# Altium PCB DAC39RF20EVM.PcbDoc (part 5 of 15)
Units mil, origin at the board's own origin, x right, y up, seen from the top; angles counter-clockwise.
Board outline 6200 x 2716.54 mil, 16 copper layers (Top Layer, L2 GND, L3 PWR, L4 GND, L5 PWR, L6 GND, L7 SIG, L8 GND, L9 GND, L10 SIG, L11 GND, L12 PWR, L13 GND, L14 PWR, L15 GND, Bottom Layer), stack 76.97 mil thick; 766 components, 495 nets, 3414 pads, 2373 vias.
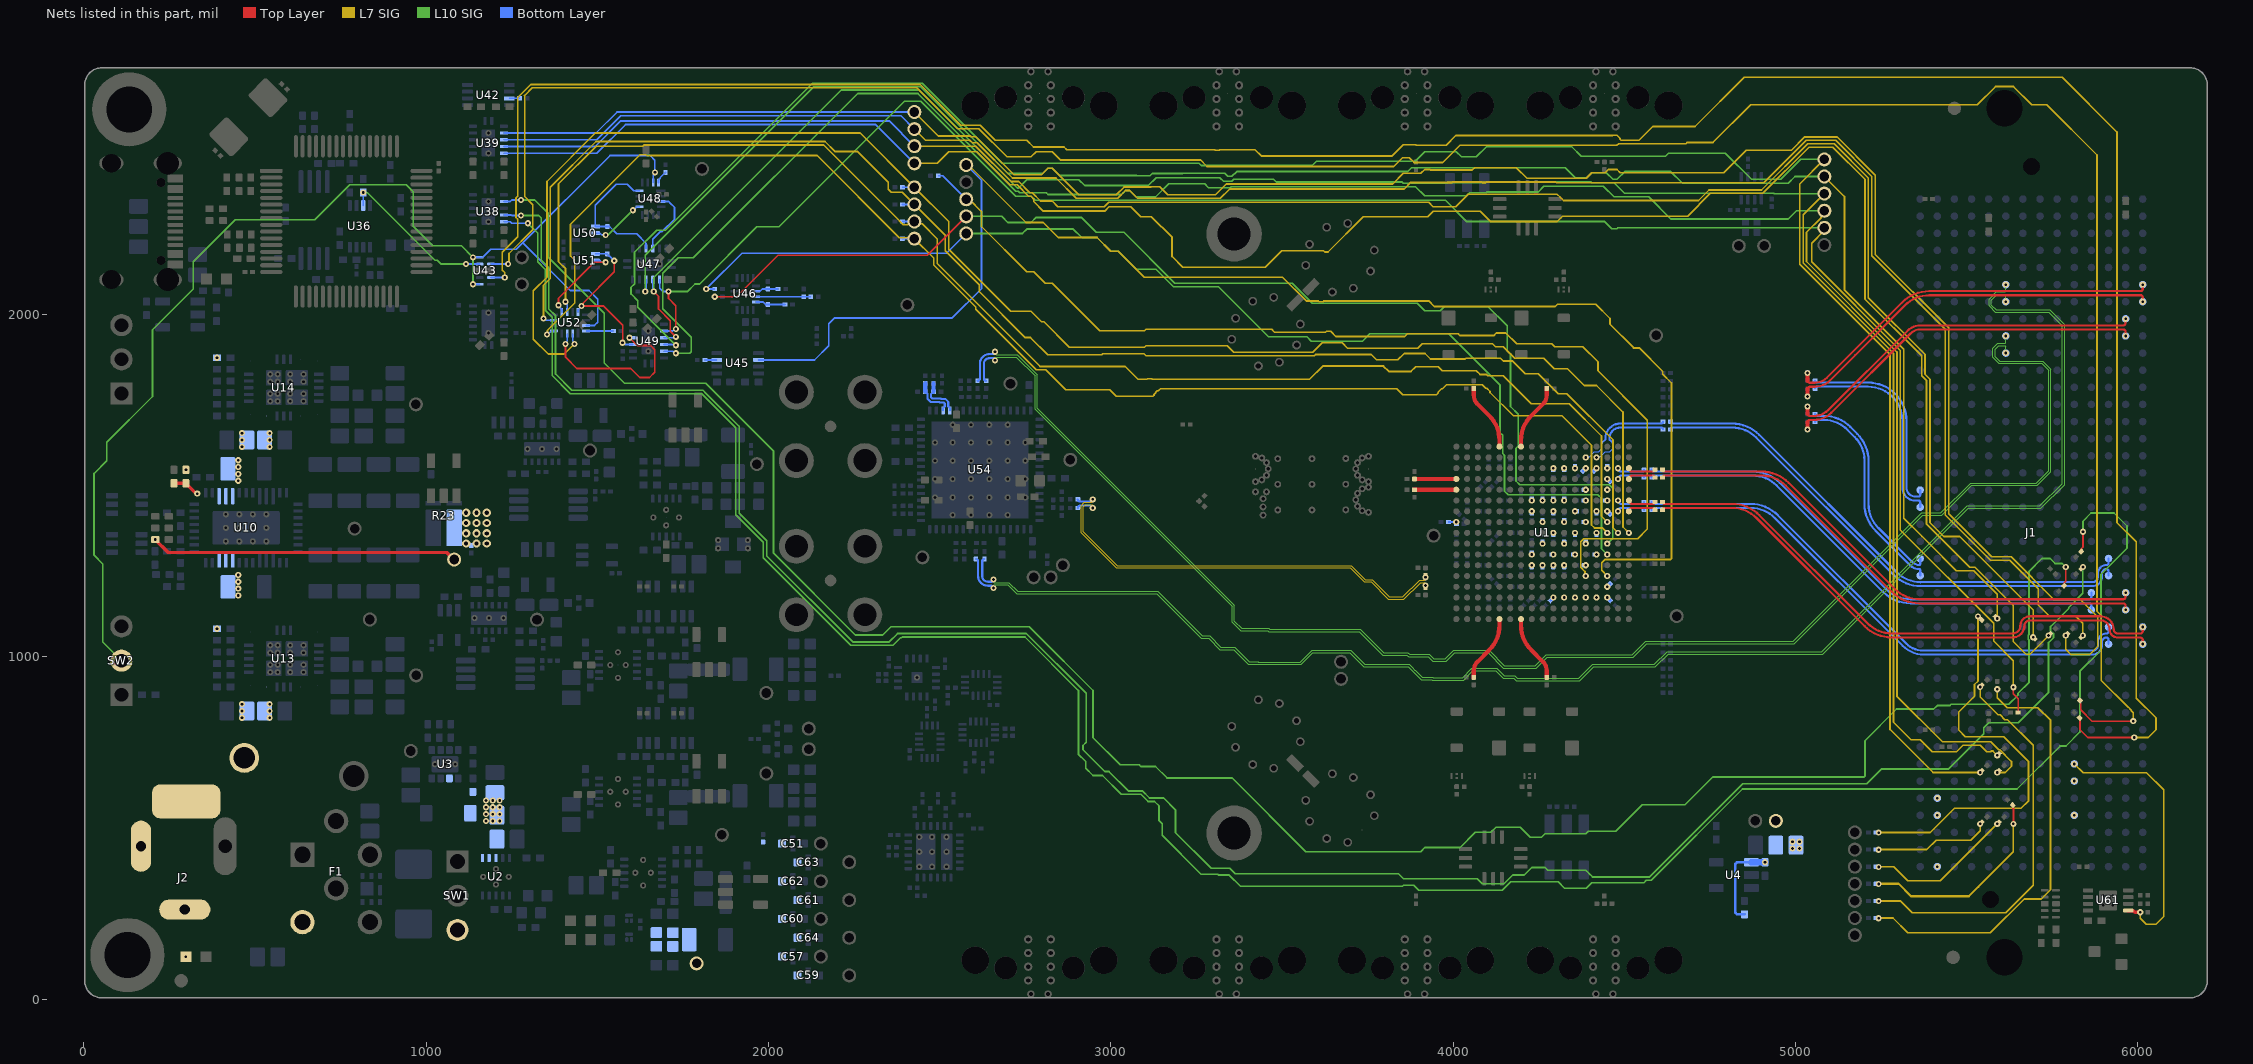
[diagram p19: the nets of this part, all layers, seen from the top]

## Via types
v1: diameter 18, hole 8, Top Layer to Bottom Layer, tented both sides, 2344 vias
v2: diameter 24, hole 12, Top Layer to Bottom Layer, tented both sides, 19 vias
v3: diameter 18, hole 8, Top Layer to Bottom Layer, tented bottom, 9 vias
v4: diameter 20, hole 10, Top Layer to Bottom Layer, tented both sides, 1 vias

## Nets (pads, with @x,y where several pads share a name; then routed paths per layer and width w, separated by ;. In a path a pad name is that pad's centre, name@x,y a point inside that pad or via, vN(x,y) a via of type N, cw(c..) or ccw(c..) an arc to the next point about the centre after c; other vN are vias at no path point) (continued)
11SRX_DUT_n: C208.1 U1.T4 | length 269.4
  Bottom Layer w3.4: 4448.05,1598.19 4456.65,1598.19 4465.77,1607.3 4465.77,1624.99
  Bottom Layer w3.5: v1(4418.48,1582.44) 4420.44,1584.41 4429.66,1584.41 4443.45,1598.19 4448.05,1598.19
  Bottom Layer w5.6: 4456.86,1633.65 4465.77,1624.99 4465.82,1624.93
  Bottom Layer w6.3: 4456.26,1634.24 4456.26,1637.85 cw(c4487.95,1637.85) 4487.95,1669.54 4607.36,1669.54 cw(c4607.36,1663.94) C208.1@4612.96,1663.94
11SRX_DUT_p: C207.1 U1.T5 | length 288.3
  Bottom Layer w3.4: 4416.56,1598.19 4425.16,1598.19 4434.27,1607.3 4434.27,1624.99
  Bottom Layer w3.5: v1(4386.98,1582.44) 4388.95,1584.41 4398.17,1584.41 4411.95,1598.19 4416.55,1598.19
  Bottom Layer w5.6: 4434.32,1624.93 4443.87,1633.73
  Bottom Layer w6.3: 4444.46,1634.33 4444.46,1637.85 cw(c4487.95,1637.85) 4487.95,1681.34 4607.36,1681.34 ccw(c4607.36,1686.94) C207.1@4612.96,1686.94
11SRX_n: C208.2 J1.A23 | length 1513.7
  Bottom Layer w6.3: C208.2@4635.01,1663.94 cw(c4640.61,1663.94) 4640.61,1669.54 4814.42,1669.54 cw(c4814.42,1569.54) 4885.13,1640.25 5286.25,1239.13 ccw(c5365.31,1318.18) 5365.31,1206.38 5867.19,1206.38 ccw(c5867.18,1234.25) 5895.03,1234.25 5895.03,1243.49 cw(c5907.71,1243.49) 5907.71,1256.17 cw(c5907.71,1249.86) 5914.01,1249.86 J1.A23@5914.01,1237.07
11SRX_p: C207.2 J1.A22 | length 1513.8
  Bottom Layer w6.3: C207.2@4635.01,1686.94 ccw(c4640.61,1686.94) 4640.61,1681.34 4814.42,1681.34 cw(c4814.42,1569.54) 4893.48,1648.59 5294.6,1247.47 ccw(c5365.31,1318.18) 5355.48,1218.67 5362.13,1218.01 ccw(c5364.01,1237.07) 5366.78,1218.12 cw(c5367.68,1211.88) 5367.68,1218.18 5867.19,1218.18 ccw(c5864.01,1237.07) 5867.31,1218.2 ccw(c5867.31,1234.12) 5883.23,1234.12 5883.23,1243.49 cw(c5907.71,1243.49) 5907.71,1267.97 ccw(c5907.71,1274.27) 5914.01,1274.27 J1.A22@5914.01,1287.07
12SRX_DUT_n: C210.1 U1.P1 | length 85
  Top Layer w6.3: U1.P1@4512.96,1519.45 cw(c4522.81,1519.45) 4522.81,1529.3 4583.51,1529.3 cw(c4583.51,1523.65) C210.1@4589.16,1523.65
12SRX_DUT_p: C209.1 U1.R1 | length 85
  Top Layer w6.3: U1.R1@4512.96,1550.94 ccw(c4522.81,1550.94) 4522.81,1541.1 4583.61,1541.1 ccw(c4583.61,1546.65) C209.1@4589.16,1546.65
12SRX_n: C210.2 J1.Z25 | length 1517.4
  Top Layer w6.3: C210.2@4611.21,1523.65 cw(c4616.81,1523.65) 4616.81,1529.25 4900.54,1529.25 cw(c4900.54,1429.25) 4971.25,1499.96 5282.29,1188.91 ccw(c5361.35,1267.97) 5361.35,1156.17 5956.65,1156.17 cw(c5956.65,1148.8) 5964.01,1148.8 v1(5964.01,1137.07)
12SRX_p: C209.2 J1.Z24 | length 1517.4
  Top Layer w6.3: C209.2@4611.21,1546.65 ccw(c4616.81,1546.65) 4616.81,1541.05 4900.54,1541.05 cw(c4900.54,1429.25) 4979.59,1508.3 5290.64,1197.26 ccw(c5361.35,1267.97) 5361.35,1167.97 5956.65,1167.97 ccw(c5956.65,1175.33) 5964.01,1175.33 v1(5964.01,1187.07)
12V: C2.2 C3.2 C6.2 C7.2 C20.2 C21.2 C32.2 C33.2 C40.2 C41.2 D1.1 D3.1 pad.1@2940.17,477.52 R7.1 R8.2 R9.2 R21.2 R34.2 R39.2 U2.6 U2.7 U2.8 U3.2 U4.1 U10.4 U10.5 U10.6 U10.33 U10.34 U10.35 U13.18 U14.18 | length 259.4
  Bottom Layer w8: R9.2@4850.49,247.76 4829.33,247.76 4824.08,253.02 4824.08,395.2 4828.76,399.89 U4.1@4870.77,399.89
  Bottom Layer w20: U4.1@4870.77,399.89 v1(4910.77,399.89)
  other v1: 297.92,123.65 4991.22,439.74 5011.22,439.74 4991.22,459.74 5011.22,459.74 1174.67,520.44 1194.67,520.44 1214.67,520.44 1174.67,540.44 1194.67,540.44 1214.67,540.44 1174.67,560.44 1194.67,560.44 1214.67,560.44 1174.67,580.44 1194.67,580.44 1214.67,580.44 461.82,821.74 542.82,821.74 461.82,841.74 542.82,841.74 461.82,861.74 542.82,861.74 389.38,1082.11 450.94,1179.07 450.94,1199.07 450.94,1219.07 450.94,1239.07 450.94,1514.11 450.94,1534.11 298.22,1546.25 450.94,1554.11 450.94,1574.11 461.82,1613.27 542.82,1613.27 461.82,1633.27 542.82,1633.27 461.82,1653.27 542.82,1653.27 389.38,1873.64
12V_FMC: J1.C35 J1.C37 J1.L36 J1.L37 J1.L40 pad.1@3598.23,258.31 SW1.3
  other v1: 5414.01,387.07 5414.01,537.07 5814.01,537.07 5414.01,587.07 5814.01,637.07
13SRX_DUT_n: C212.1 U1.P2 | length 85
  Bottom Layer w6.3: v1(4481.47,1519.45) cw(c4491.32,1519.45) 4491.32,1529.3 4552.07,1529.3 cw(c4552.07,1523.7) C212.1@4557.67,1523.7
13SRX_DUT_p: C211.1 U1.R2 | length 85
  Bottom Layer w6.3: v1(4481.47,1550.94) ccw(c4491.32,1550.94) 4491.32,1541.1 4552.07,1541.1 ccw(c4552.07,1546.7) C211.1@4557.67,1546.7
13SRX_n: C212.2 J1.B25 | length 1449.6
  Bottom Layer w6.3: C212.2@4579.48,1523.7 cw(c4585.08,1523.7) 4585.08,1529.3 4874.43,1529.3 cw(c4874.43,1429.3) 4945.14,1500.01 5256.23,1188.91 ccw(c5335.29,1267.97) 5335.29,1156.17 5857.71,1156.17 cw(c5857.71,1149.86) 5864.01,1149.86 J1.B25@5864.01,1137.07
13SRX_p: C211.2 J1.B24 | length 1449.6
  Bottom Layer w6.3: C211.2@4579.48,1546.7 ccw(c4585.08,1546.7) 4585.08,1541.1 4874.43,1541.1 cw(c4874.43,1429.3) 4953.48,1508.35 5264.58,1197.26 ccw(c5335.29,1267.97) 5335.29,1167.97 5857.71,1167.97 ccw(c5857.71,1174.27) 5864.01,1174.27 J1.B24@5864.01,1187.07
14SRX_DUT_n: C214.1 U1.L1 | length 85
  Top Layer w6.3: U1.L1@4512.96,1424.96 cw(c4522.81,1424.96) 4522.81,1434.81 4583.51,1434.81 cw(c4583.51,1429.16) C214.1@4589.16,1429.16
14SRX_DUT_p: C213.1 U1.M1 | length 85
  Top Layer w6.3: U1.M1@4512.96,1456.46 ccw(c4522.81,1456.46) 4522.81,1446.61 4583.61,1446.61 ccw(c4583.61,1452.16) C213.1@4589.16,1452.16
14SRX_n: C214.2 J1.Y27 | length 1626.6
  Top Layer w6.3: C214.2@4611.21,1429.16 cw(c4616.81,1429.16) 4616.81,1434.76 4815.01,1434.76 cw(c4815.01,1334.76) 4885.72,1405.47 5201.81,1089.39 ccw(c5280.86,1168.44) 5280.86,1056.64 5634.52,1056.64 ccw(c5634.52,1090.22) 5668.1,1090.22 cw(c5684.31,1090.22) 5684.31,1106.43 5890.92,1106.43 cw(c5890.92,1080.06) 5917.28,1080.06 ccw(c5941.18,1080.06) 5941.18,1056.17 6006.65,1056.17 cw(c6006.65,1048.8) 6014.01,1048.8 v1(6014.01,1037.07)
14SRX_p: C213.2 J1.Y26 | length 1626.6
  Top Layer w6.3: C213.2@4611.21,1452.16 ccw(c4616.81,1452.16) 4616.81,1446.56 4815.01,1446.56 cw(c4815.01,1334.76) 4894.07,1413.81 5210.15,1097.73 ccw(c5280.86,1168.44) 5280.86,1068.44 5634.52,1068.44 ccw(c5634.52,1090.22) 5656.3,1090.22 cw(c5684.31,1090.22) 5684.31,1118.23 5890.92,1118.23 cw(c5890.92,1080.06) 5929.08,1080.06 ccw(c5941.18,1080.06) 5941.18,1067.97 6006.65,1067.97 ccw(c6006.65,1075.33) 6014.01,1075.33 v1(6014.01,1087.07)
15SRX_DUT_n: C216.1 U1.L2 | length 85
  Bottom Layer w6.3: v1(4481.47,1424.96) cw(c4491.32,1424.96) 4491.32,1434.81 4552.07,1434.81 cw(c4552.07,1429.21) C216.1@4557.67,1429.21
15SRX_DUT_p: C215.1 U1.M2 | length 85
  Bottom Layer w6.3: v1(4481.47,1456.46) ccw(c4491.32,1456.46) 4491.32,1446.61 4552.07,1446.61 ccw(c4552.07,1452.21) C215.1@4557.67,1452.21
15SRX_n: C216.2 J1.A27 | length 1555.8
  Bottom Layer w6.3: C216.2@4579.72,1429.21 cw(c4585.31,1429.21) 4585.31,1434.81 4868.79,1434.81 cw(c4868.79,1334.81) 4939.5,1405.52 5313.14,1031.88 ccw(c5374.65,1093.4) 5374.65,1006.4 5867.18,1006.4 ; J1.A27@5914.01,1037.07 5914.01,1049.86 ccw(c5907.71,1049.86) 5907.71,1056.17 ccw(c5907.71,1043.49) 5895.03,1043.49 5895.03,1034.25 cw(c5867.18,1034.25) 5867.31,1006.4 ; 5867.18,1006.4 ccw(c5867.18,1034.25) 5867.31,1006.4 ; 5867.18,1006.4 5867.31,1006.4
15SRX_p: C215.2 J1.A26 | length 1555.9
  Bottom Layer w6.3: C215.2@4579.72,1452.21 ccw(c4585.31,1452.21) 4585.31,1446.61 4868.79,1446.61 cw(c4868.79,1334.81) 4947.85,1413.86 5322.93,1038.78 ccw(c5372.6,1088.46) 5372.6,1018.2 5867.31,1018.2 ccw(c5867.31,1034.12) 5883.23,1034.12 5883.23,1043.49 cw(c5907.71,1043.49) 5907.71,1067.97 ccw(c5907.71,1074.27) 5914.01,1074.27 J1.A26@5914.01,1087.07
+1p8V: C51.1 C53.2 C54.2 C55.2 C56.2 C57.1 C59.1 C60.1 C61.1 C62.1 C63.1 C64.1 FB3.2 PP14.1 R43.1
C8_N: C171.2 R167.2 U54.52 | length 127.2
  Bottom Layer w6.3: R167.2@2481.85,1774.06 2481.06,1774.06 2474.91,1767.9 2474.91,1758.31 2478.6,1754.62 2502.76,1754.62 2503.9,1753.48 2516.01,1753.48 2524.91,1744.59 2524.91,1730.64 2529.6,1725.95 U54.52@2529.6,1719.06
  Bottom Layer w12.1: R167.2@2481.85,1774.06 C171.2@2481.85,1799.06
C8_P: C170.2 R166.2 U54.51 | length 127.2
  Bottom Layer w6.3: R166.2@2457.67,1774.06 2458.45,1774.06 2464.61,1767.9 2464.61,1754.04 2474.33,1744.32 2498.5,1744.32 2499.63,1743.18 2511.74,1743.18 2514.61,1740.32 2514.61,1730.64 2509.92,1725.95 U54.51@2509.92,1719.06
  Bottom Layer w12.1: R166.2@2457.67,1774.06 C170.2@2457.67,1799.06
CCLK_SHIFT: R199.1 U38.14 | length 7112
  Top Layer w5: R199.1@5834.82,1313.25 R199.1@5834.31,1307.36 5834.86,1307.92 5834.86,1316.31 5839.32,1320.76 v3(5839.32,1365.17)
  L10 SIG w5: v1(1297.12,2266.32) 1325.64,2237.8 1325.64,2154.13 1348.36,2131.42 1348.36,2011.71 1368.04,1992.03 1368.04,1821.72 1421.02,1768.73 1804.5,1768.73 1904.37,1668.86 1904.37,1414.88 1984.81,1334.45 1984.81,1289.12 2240.49,1033.44 2363.77,1033.44 2385.55,1055.23 2387.51,1055.23 2390.28,1057.99 2748.98,1057.99 2905.22,901.76 2905.22,715.62 2926.52,694.32 2926.52,674.67 2947.83,653.37 2975.52,653.37 3030.61,598.28 3087.87,598.28 3108.66,577.49 3127.51,577.49 3140.85,564.15 3140.85,521.17 3149.97,512.05 3149.97,478.41 3263.16,365.22 3312.26,365.22 3315.08,362.4 3346.1,362.4 3378.76,329.74 3851.4,329.74 3854.72,333.05 3884.16,333.05 3899.32,317.89 4143.1,317.89 4168.11,342.9 4306.47,342.9 4325.02,324.35 4388.63,324.35 4404.48,340.21 4557.15,340.21 4564.03,347.09 4578.17,347.09 4844.79,613.71 5646.83,613.71 5772.57,739.45 5789.73,739.45 5830.51,780.23 5830.51,958.21 5891.94,1019.64 5891.94,1240.6 5968.05,1316.71 5968.05,1382.18 5930.22,1420.01 5863.05,1420.01 5839.32,1396.28 v3(5839.32,1365.17)
  Bottom Layer w5: U38.14@1227.12,2270.82 1245.54,2270.82 1250.04,2266.32 v1(1297.12,2266.32)
COMM_MUX_CTRL: SW2.1 U43.1 U43.5 U48.15 U52.15 | length 3594.9
  L10 SIG w5: SW2.1@110.07,988.8 55.54,1043.33 55.54,1270.86 30.09,1296.31 30.09,1535.41 67.3,1572.61 67.3,1626.74 200.74,1760.19 200.74,1955.14 319.86,2074.26 319.86,2154.03 442.44,2276.61 674.3,2276.61 776.63,2378.94 809.46,2378.94 942.2,2378.94 962.59,2358.54 962.59,2257.4 1019.77,2200.22 1103.12,2200.22 v1(1136.57,2166.77) v1(1136.57,2088.03)
  Bottom Layer w5: v1(1136.57,2088.03) U43.1@1156.57,2088.03 ; v1(1136.57,2166.77) U43.5@1156.57,2166.77 1164.93,2166.77 1188.43,2190.27 1263.35,2190.27 1282,2208.91 ; U52.15@1467.36,1967.47 1491.42,1967.47 1501.4,1977.45 1501.4,2043.9 1475.54,2069.75 1421.16,2069.75 1287.67,2203.24 1282,2208.91 ; U48.15@1663.11,2384.99 1663.11,2406.48 1668.11,2411.48 v1(1668.11,2414.99) 1668.11,2450.49 1653.89,2464.71 1649.75,2464.71 1649.2,2464.16 1537.24,2464.16 1282,2208.91
DAC_ALARM: PP56.1 U1.E3 U45.6 | length 4267.9
  L7 SIG w5: PP56.1@2577.51,2436.45 2584,2436.45 2752.11,2268.34 2802.58,2268.34 2846.31,2224.6 2959.58,2224.6 2999.22,2184.97 3021.62,2184.97 3097.57,2109.03 3501.49,2109.03 3571.03,2039.49 3605.64,2039.49 3607.89,2037.24 3619.9,2037.24 3622.15,2039.49 3928.53,2039.49 3944.93,2023.09 4298,2023.09 4304.68,2029.77 4416.5,2029.77 4458.03,1988.24 4458.03,1970.98 4526.8,1902.21 4543.26,1902.21 4612.03,1833.44 4612.03,1825.28 4637.61,1799.71 4637.61,1287.41 4634.68,1284.48 4443.63,1284.48 4433.47,1274.31 4433.47,1252.48 v1(4449.97,1235.98)
  Bottom Layer w5: U45.6@1971.03,1867.08 2134.21,1867.08 2175.99,1908.85 2175.99,1972.47 2193.33,1989.82 2534.02,1989.82 2535.13,1988.71 2621.96,2075.54 2621.96,2392 PP56.1@2577.51,2436.45
DAC_ALARM_FMC: R210.1 U45.3 | length 35
  Bottom Layer w5: R210.1@1813.98,1867.08 U45.3@1848.98,1867.08
DAC_C\S\: PP45.1 R151.2 U1.K3 U52.10 | length 4219.5
  L7 SIG w5: v1(1407.24,2036.84) 1407.24,2133.05 1386.49,2153.8 1386.49,2381.45 1496.43,2491.38 1632.57,2491.38 1636.36,2495.16 2160.72,2495.16 2370,2285.88 2370.08,2285.88 2393.83,2262.14 2407.14,2262.14 2416.38,2271.38 PP45.1@2426.12,2271.38 2433.01,2264.49 2448.58,2264.49 2492.73,2220.34 2492.73,2148.61 2793.22,1848.12 3041.68,1848.12 3079.31,1810.49 3105,1810.49 3107.04,1812.53 3119.05,1812.53 3121.09,1810.49 3580.16,1810.49 3618.78,1849.11 3796.01,1849.11 3811.53,1833.59 3876.8,1833.59 3890.67,1847.46 3955.94,1847.46 3967.64,1835.76 4067.17,1835.76 4078.09,1824.84 4096.13,1824.84 4100.37,1820.59 4145.7,1820.59 4227.43,1738.86 4339.17,1738.86 4432.98,1645.06 4432.98,1410.46 v1(4449.97,1393.46)
  Bottom Layer w5: v1(1407.24,2036.84) 1407.24,2033.33 1412.24,2028.33 U52.10@1412.24,2006.84 ; R151.2@2391.12,2271.38 PP45.1@2426.12,2271.38
DAC_R\E\S\E\T\: PP61.1 R135.2 U1.E5 | length 3060.8
  L7 SIG w5: PP61.1@2577.51,2336.45 2585.94,2336.45 2621.96,2300.42 2621.96,2256.86 2754.48,2124.34 2774.99,2124.34 2807.93,2091.4 2828.53,2091.4 2967.71,1952.22 3098.42,1952.22 3102.52,1956.32 3469.83,1956.32 3477.95,1948.2 3627.03,1948.2 3629.77,1950.94 3641.78,1950.94 3657.3,1935.42 3858.03,1935.42 3866.11,1943.49 4014.43,1943.49 4019.75,1938.16 4117.85,1938.16 4125.65,1945.96 4153.35,1945.96 4185.25,1914.07 4287.71,1914.07 4296.18,1905.6 4378.67,1905.6 4422.9,1861.37 4422.9,1835.25 4566.92,1691.23 4566.92,1373.11 4538.78,1344.97 4380.97,1344.97 4372.48,1336.48 4372.48,1261.47 4384.61,1249.34 4384.61,1238.35 v1(4386.98,1235.98)
  Bottom Layer w5: R135.2@2495.58,2404.99 2508.97,2404.99 PP61.1@2577.51,2336.45
DAC_R\E\S\E\T\_FMC: R134.2 R214.1 U46.12 | length 87.8
  Bottom Layer w5: U46.12@1963.15,2036.08 1984.22,2036.08 1991.07,2029.23 R134.2@1998.15,2029.23 R214.1@2048.15,2029.23
DAC_SCLK: PP42.1 R154.1 U1.J1 U52.2 | length 4678.2
  L7 SIG w5: v1(1432.99,1913.85) 1403.48,1884.34 1356.25,1884.34 1312.73,1927.87 1312.73,2068.77 1352.87,2108.92 1352.87,2388.46 1494.29,2529.88 2267.63,2529.88 PP42.1@2426.12,2371.38 2526.19,2271.32 2526.19,2190.3 2707.15,2009.34 2766.5,2009.34 2797.54,1978.29 2804.63,1978.29 2878.7,1904.22 3098.42,1904.22 3102.52,1908.32 3339.78,1908.32 3358.78,1889.32 3589.95,1889.32 3617.63,1916.99 3675.72,1916.99 3691.24,1901.47 3896.73,1901.47 3909.32,1914.07 4114.81,1914.07 4123.27,1905.6 4145.79,1905.6 4179.21,1872.19 4264.26,1872.19 4294.69,1841.76 4333.62,1841.76 4382.91,1792.46 4418.31,1792.46 4495.97,1714.81 4495.97,1378.96 v1(4512.96,1361.97)
  Bottom Layer w5: U52.2@1427.99,1943.85 1427.99,1922.37 1432.99,1917.37 v1(1432.99,1913.85) ; R154.1@2391.12,2371.38 PP42.1@2426.12,2371.38
DAC_SDI: PP43.1 R155.1 U1.J3 U52.5 | length 4186.7
  L7 SIG w5: v1(1352.87,1941.73) 1354.3,1943.15 1354.3,1953.64 1433.88,2033.22 1433.88,2158.58 1421.52,2170.94 1421.52,2262.95 1624.74,2466.16 1642.24,2466.16 1643.95,2464.45 2141.51,2464.45 2381.78,2224.19 2423.32,2224.19 PP43.1@2426.12,2221.38 2482.73,2164.77 2482.73,2144.47 2605.68,2021.53 2605.68,2014.95 2782.5,1838.12 2809.88,1838.12 2867.76,1780.24 2996.51,1780.24 3015.61,1761.13 3123.06,1761.13 3126.27,1764.35 3126.27,1767.18 3135.94,1776.84 3138.76,1776.84 3145.15,1783.23 3835.21,1783.23 3852.73,1765.71 3951.14,1765.71 3956.17,1770.74 3956.17,1773.57 3965.84,1783.23 3968.66,1783.23 3980.28,1794.85 4084.83,1794.85 4095.03,1784.65 4097.85,1784.65 4107.52,1774.99 4107.52,1772.16 4175.86,1703.81 4248.28,1703.81 4248.94,1704.47 4262.61,1704.47 4263.26,1703.81 4317.61,1703.81 4403.98,1617.45 4403.98,1385.08 4412.59,1376.47 4435.47,1376.47 v1(4449.97,1361.97)
  Bottom Layer w5: v1@1355,1941.73 1365,1951.73 U52.5@1372.87,1951.73 ; R155.1@2391.12,2221.38 PP43.1@2426.12,2221.38
DAC_SDO: PP44.1 R156.1 U1.J2 U52.7 | length 4329.8
  L7 SIG w5: v1(1342.87,1988.22) 1342.87,2084.78 1362.87,2104.78 1362.87,2371.97 1496.07,2505.16 2164.86,2505.16 2193.9,2476.13 2259.33,2476.13 2349.58,2385.88 2349.58,2365.38 2358.07,2356.88 2390.62,2356.88 PP44.1@2426.12,2321.38 2516.19,2231.32 2516.19,2186.16 2615.74,2086.61 2615.74,2066.83 2750.22,1932.36 2765.14,1932.36 2815.43,1882.07 2973.57,1882.07 2976.72,1885.22 3096.63,1885.22 3102.52,1879.32 3594.1,1879.32 3597.83,1883.05 3760.22,1883.05 3775.74,1867.53 3838.3,1867.53 3856.79,1886.02 3917.5,1886.02 3933.76,1869.76 4034.77,1869.76 4037.19,1872.19 4138.2,1872.19 4146.68,1863.7 4173.55,1863.7 4210.23,1827.02 4248,1827.02 4306.48,1768.54 4331.51,1768.54 4466.47,1633.58 4466.47,1376.96 v1(4481.47,1361.97)
  Bottom Layer w5: v1(1342.87,1988.22) 1346.39,1988.22 1351.39,1983.22 U52.7@1372.87,1983.22 ; R156.1@2391.12,2321.38 PP44.1@2426.12,2321.38
DAC_SYSREF_LMK_N: C163.1 R173.2 | length 1271.8
  Top Layer w8: v1(3919.03,1232.33) R173.2@3919.03,1237.33
  L7 SIG w3: v1(2946.87,1434.88) 2946.87,1442.15 2945.11,1443.9 2925.16,1443.9 2919.89,1438.64 2919.89,1365.56 3018.88,1266.58 3701.76,1266.58 3742.77,1225.57 3763.11,1225.57 3813.47,1175.22 3852.97,1175.22 3901.49,1223.74 3917.27,1223.74 3919.03,1225.49 v1(3919.03,1232.33)
  Bottom Layer w6.3: C163.1@2903.46,1434.88 cw(c2910.08,1434.88) 2910.08,1441.5 2940.24,1441.51 cw(c2940.24,1434.88) v1(2946.87,1434.88)
DAC_SYSREF_LMK_P: C162.1 R171.2 | length 1295
  Top Layer w8: R171.2@3919.03,1203.14 v1(3919.03,1208.14)
  L7 SIG w3: v1(2946.87,1459.93) 2946.87,1452.66 2945.11,1450.9 2922.26,1450.9 2912.89,1441.54 2912.89,1362.66 3015.98,1259.58 3698.86,1259.58 3739.87,1218.57 3760.21,1218.57 3810.57,1168.22 3855.87,1168.22 3904.39,1216.74 3917.27,1216.74 3919.03,1214.98 v1(3919.03,1208.14)
  Bottom Layer w6.3: C162.1@2903.46,1459.93 ccw(c2910.08,1459.93) 2910.08,1453.3 2940.24,1453.3 ccw(c2940.24,1459.93) v1(2946.87,1459.93)
DAC_TXEN0: PP63.1 R137.2 U1.G3 | length 3400.2
  L10 SIG w5: PP63.1@2577.51,2236.45 2741.6,2236.45 2754.48,2249.34 2890.08,2249.34 2914.82,2224.6 2959.58,2224.6 2999.22,2184.97 3021.62,2184.97 3074.7,2131.9 3131.84,2131.9 3182.9,2080.84 3314.44,2080.84 3460.28,1934.99 3572.68,1934.99 3585.74,1921.94 3735.11,1921.94 3756.67,1943.49 3987.34,1943.49 4136.38,1794.45 4136.38,1655.09 4144.36,1647.11 4144.36,1593.6 4149.51,1588.45 4149.51,1484.44 4160.5,1473.45 4421.99,1473.45 4432.98,1462.46 4432.98,1315.97 v1(4449.97,1298.98)
  Bottom Layer w5: v1(1818.11,2074.43) v1@1818.9,2074.43 ; R137.2@1843.11,2074.43 v1@1818.9,2074.43 ; PP63.1@2577.51,2236.45 2519.86,2178.8 1922.49,2178.8 1822.7,2079.01 1822.7,2078.22 v1@1818.9,2074.43
DAC_TXEN0_FMC: R132.2 R212.1 U46.10 | length 67.8
  Bottom Layer w5: U46.10@1963.15,2067.58 1974.96,2067.58 1981.81,2074.43 R132.2@1998.15,2074.43 R212.1@2028.15,2074.43
DAC_TXEN1: PP64.1 R136.2 U1.H3 | length 3495.8
  Top Layer w5: v1(1843.11,2051.83) 1906.44,2051.83 2027.51,2172.9 2463.96,2172.9 PP64.1@2577.51,2286.45
  L10 SIG w5: PP64.1@2577.51,2286.45 2680.85,2286.45 2698.96,2268.34 2766.5,2268.34 2781.55,2283.4 2913.75,2283.4 2957.41,2239.74 3038.14,2239.74 3187.05,2090.84 3529.89,2090.84 3588.42,2032.3 3894.71,2032.3 3916.52,2010.49 3962.12,2010.49 3974.03,2022.4 4101.44,2022.4 4129.4,1994.43 4130.05,1994.43 4158.02,1966.46 4158.02,1893.38 4167.19,1884.21 4167.19,1731.23 4189.89,1708.53 4189.89,1615.58 4183.5,1609.2 4183.5,1513.44 4194.49,1502.45 4455.98,1502.45 4466.2,1492.24 4466.2,1346.7 v1(4449.97,1330.47)
DAC_TXEN1_FMC: R133.2 R213.1 U46.11 | length 160
  Bottom Layer w5: U46.11@1963.15,2051.83 R133.2@2102.61,2051.83 R213.1@2123.15,2051.83
DACCLK_N: C190.1 C192.2 U1.P17 | length 122.2
  Top Layer w12.3: C190.1@3886.85,1519.45 U1.P17@4009.03,1519.45
DACCLK_P: C183.2 C186.1 U1.N17 | length 122.2
  Top Layer w12.3: C183.2@3886.85,1487.95 U1.N17@4009.03,1487.95
DACOUTA_N: R186.1 R187.1 U1.A13 | length 195.2
  Top Layer w12.1: R186.1@4060,940 4060,960 cw(c4095.87,960) 4070.51,985.36 4105.72,1020.58 ccw(c4035.01,1091.29) 4135.01,1091.29 U1.A13@4135.01,1110
DACOUTA_P: R182.1 R183.1 U1.A11 | length 195.2
  Top Layer w12.1: U1.A11@4198,1110 4198,1091.29 ccw(c4298,1091.29) 4227.29,1020.58 4262.51,985.36 cw(c4237.15,960) 4273.02,960 R182.1@4273.02,940
DACOUTB_N: R192.1 R193.1 U1.U13 | length 195.2
  Top Layer w12.1: R192.1@4060,1783.94 4060,1763.94 ccw(c4095.87,1763.94) 4070.51,1738.57 4105.72,1703.36 cw(c4035.01,1632.65) 4135.01,1632.65 U1.U13@4135.01,1613.94
DACOUTB_P: R188.1 R189.1 U1.U11 | length 195.2
  Top Layer w12.1: U1.U11@4198,1613.94 4198,1632.65 cw(c4298,1632.65) 4227.29,1703.36 4262.51,1738.57 ccw(c4237.15,1763.94) 4273.02,1763.94 R188.1@4273.02,1783.94
DIN_SHIFT: R201.1 U38.13 | length 6594.4
  Top Layer w5: R201.1@5834.31,1257.36 v3@5839.32,1262.37
  L10 SIG w5: v1(1277.12,2289.01) 1329.27,2289.01 1336.41,2281.86 1336.41,2158.59 1358.36,2136.65 1358.36,2015.86 1378.04,1996.17 1378.04,1825.86 1425.17,1778.73 1808.64,1778.73 1818.64,1768.73 1913.14,1674.23 1914.37,1673 1914.37,1419.03 1994.81,1338.59 1994.81,1305.17 1994.81,1294.46 2245.83,1043.44 2352.44,1043.44 2376.99,1067.99 2753.13,1067.99 2927.83,893.29 2927.83,750.1 2918.73,741 2918.73,728.98 2983.03,664.68 2994.36,664.68 3050.76,608.28 3092.01,608.28 3112.8,587.49 3154.01,587.49 3188.45,553.05 3188.45,486.71 3292.73,382.43 3347.23,382.43 3363.11,366.55 3840.22,366.55 3854.72,352.05 4069.9,352.05 4084.91,337.04 4148.1,337.04 4173.54,362.47 4207.36,362.47 4229.5,384.6 4268.78,384.6 4276.48,376.91 4387.49,376.91 4395.99,368.41 4395.99,367.71 4406.61,357.09 4574.03,357.09 4845.74,628.8 5207.96,628.8 5251.73,672.57 5446.92,672.57 5549.51,775.16 5549.51,793.07 5563.81,807.37 5650.36,807.37 5739.01,896.02 5739.01,1041.56 5753.51,1056.06 5753.51,1068.07 5744.65,1076.93 5744.65,1088.21 5797.51,1141.07 5797.51,1143.9 5839.01,1185.4 5839.01,1262.31 v3(5839.2,1262.49)
  Bottom Layer w5: U38.13@1227.12,2290.51 1248.54,2290.51 1250.04,2289.01 v1(1277.12,2289.01)
DONE_SHIFT: R202.1 U38.11 | length 6490.4
  Top Layer w5: R202.1@5784.31,1207.36 5784.86,1207.92 5784.86,1216.31 5789.01,1220.45 v3(5789.01,1262.37)
  L10 SIG w5: v1(1277.12,2334.38) 1317.1,2334.38 1356.41,2295.07 1356.41,2166.87 1476.46,2046.83 1519.79,2003.49 1519.79,1858.07 1579.13,1798.73 1816.92,1798.73 2014.81,1600.85 2014.81,1302.75 2254.11,1063.44 2333.07,1063.44 2357.62,1087.99 2761.41,1087.99 2780.49,1068.91 2947.83,901.57 2947.83,763.73 3026.89,684.68 3082.76,684.68 3087.68,679.76 3130.32,679.76 3163.85,646.23 3353.77,646.23 3569.22,430.78 3904.64,430.78 3916.75,442.89 4020.04,442.89 4064.39,487.24 4109.66,487.24 4124.87,502.45 4195.58,502.45 4225.29,472.74 4257.99,472.74 4268.2,482.95 4387.49,482.95 4394.62,490.07 4474.51,490.07 4551.88,567.45 4676.88,567.45 4758.23,648.8 5199.68,648.8 5202.61,651.73 5202.61,755.15 5294.76,847.31 5403.75,847.31 5413.96,857.52 5449.81,857.52 5453.86,861.57 5623.02,861.57 5649.51,888.06 5649.51,893.07 5682,925.56 5682,1048.58 5679.37,1051.2 5679.37,1063.21 5682,1065.84 5682,1249.87 5719.2,1287.07 5743.51,1287.07 5758.01,1272.57 5778.82,1272.57 v3(5789.01,1262.37)
  Bottom Layer w5: U38.11@1227.12,2329.88 1245.54,2329.88 1250.04,2334.38 v1(1277.12,2334.38)
DP14_C2M_N: J1.M19 R242.1 | length 600.7
  Bottom Layer w6.3: R242.1@5057.06,1783.42 cw(c5062.66,1783.42) 5062.66,1789.02 5211.96,1789.02 cw(c5211.96,1689.02) 5311.96,1689.02 5311.96,1493.87 ccw(c5349.66,1493.87) 5349.66,1456.17 5358.63,1456.17 cw(c5358.63,1450.79) 5364.01,1450.79 J1.M19@5364.01,1437.07
DP14_C2M_P: J1.M18 R240.1 | length 600.7
  Bottom Layer w6.3: R240.1@5057.06,1806.42 ccw(c5062.66,1806.42) 5062.66,1800.82 5211.96,1800.82 cw(c5211.96,1689.02) 5323.76,1689.02 5323.76,1493.87 ccw(c5349.66,1493.87) 5349.66,1467.97 5358.63,1467.97 ccw(c5358.63,1473.35) 5364.01,1473.35 J1.M18@5364.01,1487.07
DP15_C2M_N: J1.M23 R238.1 | length 618.1
  Bottom Layer w6.3: R238.1@5057.29,1686.18 cw(c5062.89,1686.18) 5062.89,1691.78 5082.99,1691.78 cw(c5082.99,1595.22) 5151.26,1663.51 5173.06,1641.71 cw(c5105.09,1573.75) 5201.21,1573.75 5201.21,1446.72 ccw(c5313.01,1446.72) 5233.95,1367.67 5334.79,1266.83 ccw(c5360.53,1292.57) 5360.53,1256.17 cw(c5360.53,1252.69) 5364.01,1252.69 J1.M23@5364.01,1237.07
DP15_C2M_P: J1.M22 R234.1 | length 618
  Bottom Layer w6.3: R234.1@5057.29,1709.18 ccw(c5062.89,1709.18) 5062.89,1703.58 5082.99,1703.58 cw(c5082.99,1595.22) 5159.61,1671.84 5180.26,1651.19 cw(c5101.21,1572.14) 5213.01,1572.14 5213.01,1446.72 ccw(c5313.01,1446.72) 5242.3,1376.01 5343.14,1275.17 ccw(c5360.53,1292.57) 5360.53,1267.97 ccw(c5360.53,1271.45) 5364.01,1271.45 J1.M22@5364.01,1287.07
DP20_C2M_N: J1.Z9 R237.1 | length 1074.6
  Top Layer w6.3: 5035.01,1686.23 cw(c5039.5,1686.23) 5036.33,1689.4 cw(c5042.06,1683.67) 5042.06,1691.78 5053.55,1691.78 ccw(c5053.55,1763.55) 5104.3,1712.8 5335.88,1944.37 cw(c5364.35,1915.9) 5364.35,1956.17 5956.65,1956.17 cw(c5956.65,1948.8) 5964.01,1948.8 v1(5964.01,1937.07)
  Top Layer w12.1: v1(5035.01,1664.13) 5035.01,1686.23
DP20_C2M_P: J1.Z8 R233.1 | length 1074.6
  Top Layer w6.3: 5035.01,1709.13 ccw(c5039.5,1709.13) 5036.33,1705.95 ccw(c5042.06,1711.69) 5042.06,1703.58 5053.55,1703.58 ccw(c5053.55,1763.55) 5095.96,1721.14 5327.53,1952.72 cw(c5364.35,1915.9) 5364.35,1967.97 5956.65,1967.97 ccw(c5956.65,1975.33) 5964.01,1975.33 v1(5964.01,1987.07)
  Top Layer w12.1: 5035.01,1709.13 v1(5035.01,1731.23)
DP21_C2M_N: J1.Y7 R241.1 | length 1125.2
  Top Layer w6.3: 5035.01,1783.14 cw(c5039.5,1783.14) 5036.33,1786.31 cw(c5042.06,1780.58) 5042.06,1788.69 5056.37,1788.69 ccw(c5056.37,1849.45) 5099.32,1806.47 5174.06,1881.21 5318.82,2025.97 5319.73,2026.88 cw(c5390.44,1956.17) 5390.44,2056.17 6007.71,2056.17 cw(c6007.71,2049.87) 6012.17,2054.32 cw(c6007.71,2049.87) 6014.01,2049.87 v1(6014.01,2037.07)
  Top Layer w12.1: v1(5035.01,1760.03) 5035.01,1783.14
DP21_C2M_P: J1.Y6 R239.1 | length 1125.2
  Top Layer w6.3: 5035.01,1806.04 ccw(c5039.5,1806.04) 5036.33,1802.86 ccw(c5042.06,1808.6) 5042.06,1800.49 5056.37,1800.49 ccw(c5056.37,1849.45) 5090.99,1814.83 5311.38,2035.22 cw(c5390.44,1956.17) 5390.44,2067.97 6007.71,2067.97 ccw(c6007.71,2074.27) 6012.17,2069.81 ccw(c6007.71,2074.27) 6014.01,2074.27 v1(6014.01,2087.07)
  Top Layer w12.1: 5035.01,1806.04 v1(5035.01,1829.14)
DVDD: C236.1 C237.1 C238.1 C239.1 C240.1 C241.1 C242.1 C243.1 C244.1 C245.1 C246.1 C247.1 C248.1 C249.1 C250.1 C251.1 C252.1 C253.1 C254.1 C255.1 C256.1 C257.1 C258.1 C259.1 C260.1 C261.1 C262.1 C263.1 C264.1 C265.1 C266.1 C267.1 C268.1 C269.1 C270.1 C271.1 C272.1 C273.1 C274.1 C275.1 pad.1@1988.23,2488.31 PP11.1 R22.1 R23.3 R24.2 U1.C3 U1.C4 U1.C5 U1.C6 U1.C7 U1.C8 U1.D3 U1.F5 U1.F7 U1.F8 U1.F9 U1.F10 U1.G4 U1.G6 U1.G8 U1.G10 U1.H5 U1.H7 U1.H9 U1.J4 U1.J6 U1.J8 U1.K5 U1.K7 U1.K9 U1.L3 U1.L4 U1.L6 U1.L8 U1.L10 U1.M3 U1.M5 U1.M7 U1.M8 U1.M9 U1.M10 U1.N3 U1.N5 U1.P3 U1.R3 U1.R4 U1.R5 U1.R6 U1.R7 U1.R8 | length 1131.7
  Top Layer w10: v1(208.78,1342.34) 246.45,1304.67 1060.61,1304.67 1081.21,1284.07 PP11.1@1081.93,1284.07
  Bottom Layer w5: C268.1@4229.5,1262.76 v1(4229.5,1267.48) ; v1(4229.5,1298.98) C264.1@4229.5,1303.7 ; C253.1@4229.5,1420.24 v1(4229.5,1424.96) ; v1(4229.5,1456.46) C243.1@4229.5,1461.18 ; C269.1@4261,1262.76 v1(4261,1267.48) ; v1(4261,1330.47) C258.1@4261,1335.2 ; v1(4261,1393.46) C254.1@4261,1398.19 ; v1(4261,1456.46) C244.1@4261,1461.18 ; C265.1@4287.77,1298.98 v1(4292.49,1298.98) ; C270.1@4292.49,1262.76 v1(4292.49,1267.48) ; C259.1@4292.49,1357.24 v1(4292.49,1361.97) ; C255.1@4292.49,1420.24 v1(4292.49,1424.96) ; v1(4292.49,1456.46) C245.1@4292.49,1461.18 ; C242.1@4292.49,1546.22 C242.1@4292.49,1550.94 ; C271.1@4323.99,1262.76 v1(4323.99,1267.48) ; v1(4323.99,1330.47) C260.1@4323.99,1335.2 ; v1(4323.99,1393.46) C256.1@4323.99,1398.19 ; v1(4323.99,1456.46) C246.1@4323.99,1461.18 ; C241.1@4323.99,1546.22 C241.1@4323.99,1550.94 ; C266.1@4350.76,1298.98 v1(4355.48,1298.98) ; C261.1@4355.48,1357.24 v1(4355.48,1361.97) ; v1(4355.48,1424.96) C249.1@4360.21,1424.96 ; v1(4355.48,1550.94) C240.1@4355.48,1555.67 ; C272.1@4382.26,1267.48 v1(4386.98,1267.48) ; C257.1@4382.26,1393.46 v1(4386.98,1393.46) ; C248.1@4382.26,1456.46 v1(4386.98,1456.46) ; C247.1@4382.26,1487.95 v1(4386.98,1487.95) ; v1(4386.98,1330.47) C262.1@4386.98,1335.2 ; C267.1@4413.75,1298.98 v1(4418.48,1298.98) ; C263.1@4418.48,1357.24 v1(4418.48,1361.97) ; C252.1@4418.48,1420.24 v1(4418.48,1424.96) ; C250.1@4445.25,1456.46 v1(4449.97,1456.46) ; v1(4449.97,1550.94) C237.1@4449.97,1555.67
  Bottom Layer w8: C273.1@4284.54,1165.04 v1(4292.49,1172.99) ; C239.1@4379.03,1542.99 v1(4386.98,1550.94) ; C238.1@4410.52,1542.99 v1(4418.48,1550.94) ; v1(4449.97,1172.99) C275.1@4457.93,1165.04 ; v1(4449.97,1204.49) C274.1@4457.93,1212.44 ; v1(4449.97,1424.96) C251.1@4457.93,1417.01 ; v1(4449.97,1519.45) C236.1@4457.93,1511.5
  other v1: 4323.99,1172.99 4355.48,1172.99 4386.98,1172.99 4418.48,1172.99 4449.97,1487.95 4292.49,1550.94 4323.99,1550.94
  other v2: 1116.93,1330.59 1146.93,1330.59 1176.93,1330.59 1116.93,1360.59 1146.93,1360.59 1176.93,1360.59 1116.93,1390.59 1146.93,1390.59 1176.93,1390.59 1116.93,1420.59 1146.93,1420.59 1176.93,1420.59
EN1: R21.1 R25.2 U10.1 | length 81.9
  Top Layer w10: R25.2@263.22,1506.88 R21.1@298.22,1506.88 298.22,1504.91 303.06,1500.07 305.03,1500.07 326.98,1478.12 329.85,1478.12 v1(331.38,1476.59)
EXTGND: F1.3 J2.2 J2.3 pad.1@287.86,576.82 pad.1@296.26,581.46 pad.1@297.61,578.8 pad.1@298.17,582.74 pad.1@298.22,587.41 pad.1@298.23,583.31 pad.1@299.17,577.65 pad.1@299.17,582.83 pad.1@299.44,582.74 pad.1@304.72,582.83 TP2.1
EXTR: C219.2 R179.1 U1.K17 | length 28
  Bottom Layer w6.3: R179.1@3986.03,1393.46 v1(4009.03,1393.46) C219.2@4009.03,1388.46
F2F_RST_SHIFT: R211.1 U42.7 | length 30
  Bottom Layer w5: U42.7@1242.87,2631.1 R211.1@1272.87,2631.1
F2F_SCLK_SHIFT: PP67.1 R203.1 U39.14 | length 6156.9
  Top Layer w5: v1(5739.01,1062.07) R203.1@5743.72,1066.77
  L7 SIG w5: PP67.1@2426.12,2441.38 2492.73,2441.38 2526.19,2474.84 2608.08,2474.84 2704.52,2378.4 2726.28,2378.4 2759.34,2345.34 2766.5,2345.34 2774.99,2336.84 2774.99,2329.69 2802.82,2301.86 2981.65,2301.86 2994.71,2314.92 3057.6,2314.92 3086.87,2285.65 3118.27,2285.65 3178.77,2225.14 3178.77,2169.32 3210.29,2137.8 3450.9,2137.8 3499.34,2186.24 3621.16,2186.24 3624.96,2182.43 3634.19,2182.43 3737.41,2285.65 3925.5,2285.65 3941.55,2301.7 4078.98,2301.7 4109.53,2271.15 4303.22,2271.15 4319.14,2287.07 4684.67,2287.07 4751.2,2353.6 4904.41,2353.6 5039.34,2488.53 5108.49,2488.53 5202.61,2394.42 5202.61,2044.66 5368.18,1879.09 5368.18,1821.14 5382.61,1806.71 5382.61,1387.64 5508.68,1261.57 5524.16,1261.57 5636.06,1149.67 5636.06,1044.51 5672.94,1007.63 5684.57,1007.63 v1(5739.01,1062.07)
  Bottom Layer w5: U39.14@1227.12,2470.82 1498.61,2470.82 1582.35,2554.56 2312.94,2554.56 PP67.1@2426.12,2441.38
F2F_SDI_SHIFT: PP65.1 R204.1 U39.11 | length 6197.8
  Top Layer w5: v1(5789.01,1062.07) R204.1@5793.72,1066.77
  L7 SIG w5: PP65.1@2426.12,2591.38 2496.55,2520.96 2590.24,2520.96 2592.1,2519.1 2606.24,2519.1 2716.95,2408.4 2797.52,2408.4 2816.52,2427.39 2828.53,2427.39 2906.23,2349.7 3016.09,2349.7 3038.57,2372.17 3117.36,2372.17 3118.27,2373.09 3142.48,2373.09 3165.95,2349.62 3305.64,2349.62 3336.93,2380.91 3823.19,2380.91 3854.48,2412.2 3905.23,2412.2 3916.52,2423.49 3932.32,2423.49 3933.69,2422.11 4055.85,2422.11 4062.35,2428.62 4184.51,2428.62 4215.43,2397.7 4388.41,2397.7 4404.48,2413.77 4443.58,2413.77 4453.3,2423.49 4478.53,2423.49 4487.9,2414.12 4790.35,2414.12 4856.03,2479.8 4988.18,2479.8 5026.91,2518.53 5120.92,2518.53 5232.61,2406.84 5232.61,2175.27 5447.14,1960.74 5447.14,1418.15 5573.35,1291.94 5629.66,1291.94 5754.69,1166.92 5832.1,1166.92 5882.61,1116.41 5882.61,1030.11 5859.18,1006.68 5804.02,1006.68 5789.01,1021.69 v1(5789.01,1062.07)
  Bottom Layer w5: U39.11@1227.12,2529.88 1496.19,2529.88 1557.7,2591.38 PP65.1@2426.12,2591.38
F2F_SDO_SHIFT: PP68.1 R206.1 U39.12 | length 5940.7
  Top Layer w5: R206.1@5834.31,1057.36 v1(5839.01,1062.07)
  L7 SIG w5: PP68.1@2426.12,2541.38 2458.4,2509.1 2587.95,2509.1 2595.68,2501.38 2609.82,2501.38 2712.81,2398.4 2839.8,2398.4 2898.96,2339.24 3019.78,2339.24 3042.71,2362.17 3054.72,2362.17 3077.66,2339.24 3319.89,2339.24 3347.16,2366.5 3856.79,2366.5 3875.92,2385.64 3996.53,2385.64 3997.66,2386.76 4083.39,2386.76 4084.52,2385.64 4095.26,2385.64 4096.39,2386.76 4299.71,2386.76 4301.7,2384.77 4907.29,2384.77 5031.05,2508.53 5116.78,2508.53 5222.61,2402.7 5222.61,2171.13 5437.14,1956.6 5437.14,1414.01 5569.2,1281.94 5625.52,1281.94 5708.63,1198.83 5708.63,1151.24 5741.77,1118.11 5818.66,1118.11 5839.01,1097.76 v1(5839.01,1062.07)
  Bottom Layer w5: U39.12@1227.12,2510.19 1498.56,2510.19 1568.83,2580.47 2387.04,2580.47 PP68.1@2426.12,2541.38
F2F_SEN_SHIFT: PP66.1 R205.1 U39.13 | length 5838
  Top Layer w5: v1(5693.87,1057.21) R205.1@5698.42,1052.66 R205.1@5698.58,1052.5
  L7 SIG w5: PP66.1@2426.12,2491.38 2605.68,2491.38 2708.66,2388.4 2730.43,2388.4 2763.48,2355.34 2770.64,2355.34 2794.58,2331.4 2828.53,2331.4 2845,2314.92 2980.57,2314.92 2993.39,2327.74 3928.28,2327.74 3941.1,2314.92 4007.15,2314.92 4043.55,2351.33 4303.22,2351.33 4311.72,2342.84 4311.72,2342.71 4314.65,2339.78 4315.11,2339.78 4322.03,2332.86 4716.32,2332.86 4747.06,2363.6 4900.27,2363.6 5035.19,2498.53 5112.63,2498.53 5212.61,2398.56 5212.61,2048.8 5378.18,1883.23 5378.18,1825.28 5392.61,1810.85 5392.61,1391.78 5408.58,1375.81 5432.82,1351.57 5479.01,1351.57 5693.87,1136.7 v1(5693.87,1057.21)
  Bottom Layer w5: U39.13@1227.12,2490.51 1494.03,2490.51 1568.83,2565.31 2352.2,2565.31 PP66.1@2426.12,2491.38
Fan: PP2.1 R6.1 R7.2
FMC_C\S\_DAC: PP38.1 R139.2 R227.1 U49.5 | length 6379.5
  Top Layer w5: v1(5539.01,662.07) R227.1@5543.72,666.77
  L7 SIG w5: PP38.1@5084.05,2452.9 5012.01,2380.86 5012.01,2146.13 5275.97,1882.17 5275.97,787.75 5401.65,662.07 v1(5539.01,662.07)
  L10 SIG w5: v1(1729.38,1909.86) 1618.33,2020.91 1618.33,2040.06 1598.47,2059.92 1598.47,2079.07 1608.98,2089.59 1608.98,2107.83 1608.39,2108.43 1608.39,2181.25 1673.14,2246.01 1698.95,2246.01 2128.41,2675.47 2448.81,2675.47 2682.93,2441.34 3257.52,2441.34 3263.99,2434.87 3587.98,2434.87 3600.69,2447.58 3888.7,2447.58 3916.52,2475.4 4008.9,2475.4 4024.02,2460.28 4067.65,2460.28 4098.02,2490.66 4345.35,2490.66 4374.35,2461.66 4619.98,2461.66 4628.94,2470.61 4794.93,2470.61 4871.06,2394.49 4957.1,2394.49 5015.52,2452.9 PP38.1@5084.05,2452.9
  Bottom Layer w5: U49.5@1694.38,1912.36 1719.95,1912.36 1726.9,1912.34 v1(1729.38,1909.86)
FMC_C\S\_LMK: PP36.1 R140.2 R221.1 U47.5 | length 5523.7
  Top Layer w5: R221.1@5584.31,1116.77 v1(5589.01,1112.07)
  L7 SIG w5: PP36.1@5084.05,2402.9 5142.61,2344.35 5142.61,2072.1 5315.97,1898.74 5315.97,1405.1 5369.5,1351.57 5370.02,1351.57 5428.51,1293.07 5428.51,1292.56 5469.5,1251.57 5520.02,1251.57 5589.01,1182.57 v1(5589.01,1112.07)
  L10 SIG w5: v1(1640.01,2066.83) 1640.01,2172.92 2132.55,2665.47 2444.66,2665.47 2698.48,2411.65 2800.78,2411.65 2816.52,2427.4 2828.53,2427.4 2850.41,2405.52 3075.35,2405.52 3076.14,2404.73 3114.18,2404.73 3121.11,2411.65 3209.68,2411.65 3210.21,2412.18 3332.41,2412.18 3341.36,2403.23 3353.38,2403.23 3367.4,2417.25 3866.56,2417.25 3877.92,2428.62 4326.97,2428.62 4355.97,2399.62 4390.33,2399.62 4404.48,2413.77 4447.24,2413.77 4466.52,2394.49 4478.53,2394.49 4502.61,2418.57 4634.19,2418.57 4669.56,2383.2 4978.5,2383.2 4998.21,2402.9 PP36.1@5084.05,2402.9
  Bottom Layer w5: v1(1640.01,2066.83) 1642.5,2069.32 1642.5,2076.25 U47.5@1642.51,2101.83
FMC_C\S\_LMK_3p3: R145.2 U47.12 U48.12 U50.1 | length 408.2
  Bottom Layer w5: U48.12@1623.74,2361.37 1606.33,2361.37 1587.82,2379.88 1555.41,2379.88 1494.29,2318.76 U50.1@1494.29,2256.95 R145.2@1529.29,2256.95 1535.59,2256.95 1557.15,2235.39 1614.84,2235.39 1642.19,2208.04 1642.19,2192.7 U47.12@1642.51,2192.38
FMC_CS_DAC_1p8: R149.2 U49.12 U51.1 U52.12 | length 482.1
  Top Layer w5: v1(1549.29,2156.95) 1549.29,2124.18 1458.53,2033.42 1458.53,2033.19 1453.74,2028.39 v1(1453.74,2024.88) 1517.49,2024.88 1573.83,1968.54 v1(1573.83,1917.36)
  Bottom Layer w5: U52.12@1443.74,2006.84 1443.74,2012.75 v1@1453.74,2022.75 ; U51.1@1494.29,2176.95 R149.2@1529.29,2176.95 1529.29,2176.16 1535.22,2170.23 1536.01,2170.23 v1(1549.29,2156.95) ; v1(1573.83,1917.36) 1577.35,1917.36 1582.35,1912.36 U49.12@1603.83,1912.36
FMC_I2C_SCL: R208.1 U43.7 | length 7376.1
  Top Layer w5: R208.1@5830.58,872.45 5830.58,867.08 5832.67,864.98 5832.67,845.07 5865.68,812.07 v1(5986.41,812.07)
  L7 SIG w5: v1(1239.44,2147.08) 1241.93,2149.57 1241.93,2178.13 1311.62,2247.82 1311.62,2320.38 1287.61,2344.4 1287.61,2638.8 ; 1287.18,2639.23 1309.68,2661.73 2433.01,2661.73 2552.08,2542.66 2614.48,2542.66 2696.8,2460.34 2766.5,2460.34 2781.55,2475.4 2828.53,2475.4 2852.59,2451.34 3261.66,2451.34 3280.77,2432.23 3826.38,2432.23 3851.73,2457.57 3872.02,2457.57 3885.66,2443.94 3969.74,2443.94 4019.74,2493.94 4478.08,2493.94 4483.03,2498.9 4679.79,2498.9 4682.96,2502.07 4758.53,2502.07 4868.6,2612.14 5530.34,2612.14 5583.73,2665.52 5636.29,2665.52 5689.68,2612.14 5733.99,2612.14 5880.51,2465.61 5880.51,1132.65 5892.61,1120.56 5892.61,930.83 5969.87,853.57 5970.85,853.57 5980.51,843.9 5980.51,842.92 5986.41,837.02 v1(5986.41,812.07)
  Bottom Layer w5: U43.7@1189.44,2147.08 v1(1239.44,2147.08)
FMC_I2C_SDA: R209.1 U43.9 | length 7610.6
  Top Layer w5: R209.1@5829.6,821.48 5830.16,820.92 5830.16,812.53 5830.58,812.12 5830.58,787.07 5853.35,764.29 v1(5989.02,764.29)
  L7 SIG w5: v1(1229.44,2107.71) 1229.44,2122.5 1222.61,2129.33 1222.61,2181.75 1267.61,2226.74 1267.61,2278.02 1262.62,2283 1262.62,2340.38 1267.61,2345.37 1267.61,2633.8 1305.53,2671.73 2442.8,2671.73 2561.87,2552.66 2618.62,2552.66 2662.38,2508.9 2753.93,2508.9 2773.83,2488.99 2862.94,2488.99 2870.87,2481.05 3303.36,2481.05 3304.48,2479.93 3316.5,2479.93 3317.62,2481.05 3420.87,2481.05 3438.85,2463.08 3822.01,2463.08 3854.48,2495.55 3890.93,2495.55 3892.09,2494.4 3979.58,2494.4 4008.13,2522.94 4466.06,2522.94 4466.52,2523.4 4478.53,2523.4 4487.03,2514.9 4487.03,2511.82 4489.96,2508.9 4542.61,2508.9 4582.85,2549.14 4706.11,2549.14 4849.81,2692.84 5778.57,2692.84 5938.74,2532.66 5938.74,1391.83 5994.78,1335.79 5994.78,879.29 6052.59,821.48 6052.59,787.15 6029.73,764.29 v1(5989.02,764.29)
  Bottom Layer w5: U43.9@1189.44,2107.71 v1(1229.44,2107.71)
FMC_SCLK: PP39.1 R215.1 U47.3 U49.3 | length 5653.5
  Top Layer w5: v1(1707.88,2066.83) 1707.88,2046.83 1729.38,2025.33 v1(1729.38,1957.73) ; v1(5636.06,911.22) 5636.06,891.69 5649.96,877.79 R215.1@5649.96,837.07
  L7 SIG w5: PP39.1@5084.05,2252.9 5084.05,2245.04 5047.01,2208 5047.01,2153.55 5305.97,1894.59 5305.97,1370.3 5578.51,1097.76 5578.51,1046.01 5636.06,988.47 v1(5636.06,911.22)
  L10 SIG w5: v1(1707.88,2066.83) 1762.81,2066.83 1762.89,2066.75 1785.06,2088.93 1798.94,2088.93 1966.02,2256.01 2030.49,2256.01 2397.12,2622.63 2445.07,2622.63 2722.37,2345.34 2766.5,2345.34 2778.66,2333.17 3977.31,2333.17 4039.34,2271.15 4442.61,2271.15 4463.27,2250.49 4478.53,2250.49 4480.95,2252.9 PP39.1@5084.05,2252.9
  Bottom Layer w5: U47.3@1681.88,2101.83 1681.88,2076.26 1691.31,2066.83 v1(1707.88,2066.83) ; U49.3@1694.38,1951.73 1719.95,1951.73 1725.95,1957.73 v1(1729.38,1957.73)
FMC_SCLK_DAC_1p8: R147.2 U52.16 | length 79.4
  Bottom Layer w5: U52.16@1467.36,1951.73 1509.22,1951.73 R147.2@1546.78,1951.73
FMC_SCLK_LMK_3p3: R141.2 U48.16 | length 38.7
  Bottom Layer w5: U48.16@1678.86,2384.99 1678.86,2392.87 1683.86,2397.87 1683.86,2399.99 1694.27,2410.41 1695.06,2410.41 1698.86,2414.21 R141.2@1698.86,2414.99
FMC_SDI: PP37.1 R216.1 U47.4 U49.4 | length 6136.5
  Top Layer w5: v1(1664.7,2066.83) 1664.7,2066.68 1678.77,2052.61 1678.77,2016.12 1712.88,1982.01 1712.88,1950.89 1729.23,1934.54 v1(1729.38,1934.54) ; v1(5589.01,712.07) R216.1@5593.72,716.77
  L7 SIG w5: PP37.1@5084.05,2352.9 5022.01,2290.86 5022.01,2150.27 5285.97,1886.31 5285.97,808.74 5337.2,757.52 5364.07,757.52 5399.02,722.57 5470.02,722.57 5489.02,741.57 5539.01,741.57 5558.01,722.57 5570.02,722.57 5572.19,724.74 5576.34,724.74 v1(5589.01,712.07)
  L10 SIG w5: v1(1664.7,2066.83) 1664.7,2107.71 2212.45,2655.47 2440.52,2655.47 2726.5,2369.49 2730.64,2369.49 2754.48,2393.34 2906.5,2393.34 2923.33,2376.52 3109.45,2376.52 3132.28,2399.34 3318.41,2399.34 3328.92,2388.83 3353.12,2388.83 3358.78,2394.49 3475.13,2394.49 3482.85,2386.76 3850.92,2386.76 3854.48,2383.2 3983.08,2383.2 3985.52,2385.64 4096.53,2385.64 4097.66,2386.76 4402.49,2386.76 4404.77,2384.49 4469.53,2384.49 4500.42,2353.6 4936.95,2353.6 4937.65,2352.9 PP37.1@5084.05,2352.9
  Bottom Layer w5: U47.4@1662.2,2101.83 1662.2,2076.26 1662.21,2069.32 v1(1664.7,2066.83) ; U49.4@1694.38,1932.04 1719.95,1932.04 1726.9,1932.05 v1(1729.38,1934.54)
FMC_SDI_DAC_1p8: U49.13 U52.3 | length 527
  Top Layer w5: v1(1407.24,1913.85) 1407.24,1875.06 1440.07,1842.24 1597.76,1842.24 1624.27,1815.74 1652.27,1815.74 1668.11,1831.57 1668.11,1896.92 1655.92,1909.11 1616.77,1909.11 v1(1593.83,1932.04)
  Bottom Layer w5: v1(1407.24,1913.85) 1407.24,1917.37 1412.24,1922.37 U52.3@1412.24,1943.85 ; v1(1593.83,1932.04) U49.13@1603.83,1932.04
FMC_SDI_LMK_3p3: U47.13 U48.3 | length 194.9
  Bottom Layer w5: U47.13@1662.2,2192.38 1662.2,2219.63 1684.12,2241.56 1688.52,2241.56 1725.41,2278.45 1725.41,2312.6 1713.21,2324.8 1713.21,2324.88 1708.21,2329.88 U48.3@1686.73,2329.88
FMC_SDO: PP41.1 R217.1 U49.6 | length 6219.1
  Top Layer w5: v1(5589.01,662.07) R217.1@5593.72,666.77
  L7 SIG w5: PP41.1@5084.05,2302.9 5084.05,2293.16 5074.46,2283.56 5074.46,2282.9 5032.01,2240.46 5032.01,2154.41 5295.97,1890.45 5295.97,884.6 5429.01,751.57 5570.02,751.57 5593.02,728.57 5595.85,728.57 5630.51,693.9 5630.51,680.23 5612.35,662.07 v1(5589.01,662.07)
  L10 SIG w5: v1(1729.38,1886.67) 1769.87,1886.67 1774.54,1891.35 1774.54,1933.07 1691.38,2016.23 1691.38,2120.25 1736.45,2165.33 1780.29,2165.33 2260.43,2645.47 2436.38,2645.47 2722.35,2359.49 2729.43,2359.49 2733.58,2355.34 2811.58,2355.34 2816.52,2350.4 3030.93,2350.4 3035.88,2355.34 3042.71,2362.17 3054.72,2362.17 3073.72,2343.17 3130.51,2343.17 3168.75,2381.42 3273.88,2381.42 3284.96,2370.34 3348.78,2370.34 3351.63,2373.2 3889.81,2373.2 3916.52,2346.49 4038.71,2346.49 4047.86,2355.64 4096.53,2355.64 4098.66,2357.76 4248.1,2357.76 4264.83,2374.49 4438.52,2374.49 4469.4,2343.61 4570.83,2343.61 4635.63,2278.8 4978.5,2278.8 5002.61,2302.9 PP41.1@5084.05,2302.9
  Bottom Layer w5: U49.6@1694.38,1892.67 1719.95,1892.67 1725.95,1886.67 v1(1729.38,1886.67)
FMC_SDO_DAC_1p8: U51.2 U52.9 | length 258
  Top Layer w5: v1(1386.49,2026.84) 1386.49,2047.44 1491.32,2152.26 v1(1524.29,2152.26)
  Bottom Layer w5: v1(1386.49,2026.84) 1386.49,2024.72 1396.49,2014.72 U52.9@1396.49,2006.84 ; U51.2@1494.29,2157.26 1507.48,2157.26 1512.21,2152.53 1524.02,2152.53 v1(1524.29,2152.26)
FMC_SDO_LMK_3p3: U48.9 U50.2 | length 165.4
  L10 SIG w5: v1(1524.29,2232.26) 1531.87,2232.26 v1(1603.74,2304.13)
  Bottom Layer w5: U50.2@1494.29,2237.26 1507.48,2237.26 1512.21,2232.53 1524.02,2232.53 v1(1524.29,2232.26) ; v1(1603.74,2304.13) 1605.87,2304.13 1615.87,2314.13 U48.9@1623.74,2314.13
FMC_TRIG0: R223.1 R244.1 | length 1282.2
  L7 SIG w5: v1(5242.61,236.3) 5243.24,236.94 5284.47,236.94 5327.61,193.8 5569.01,193.8 5667.55,292.34 5717.02,292.34 5744.79,320.1 5744.79,814.55 5707.77,851.57 5618.3,851.57 5589.01,880.85 v1(5589.01,905.17)
  Bottom Layer w5: R244.1@5235.05,236.94 v1@5242.61,236.94
FMC_TRIG1: R224.1 R245.1 | length 1164.7
  Top Layer w5: v1(5539.01,912.07) R224.1@5543.72,916.77
  L7 SIG w5: v1(5242.61,286.3) 5243.24,286.94 5305.89,286.94 5340.37,252.46 5613.53,252.46 5693.87,332.8 5693.87,741.39 5618.8,816.47 5611.28,816.47 5597.34,830.4 5591.18,830.4 5539.01,882.57 v1(5539.01,912.07)
  Bottom Layer w5: R245.1@5235.05,286.94 v1@5242.61,286.94
FMC_TRIG2: R218.1 R246.1 | length 607.1
  Top Layer w6.3: R218.1@5634.31,566.77 5634.86,566.22 5634.86,557.83 5636.06,556.63 v1(5636.06,512.07)
  L7 SIG w5: 5533.37,327.85 5636.06,430.54 v1(5636.06,512.07)
  L7 SIG w6.3: v1(5242.61,336.3) 5243.24,336.94 5300.89,336.94 5337.23,300.6 5506.12,300.6 5533.37,327.85
  Bottom Layer w5: R246.1@5235.05,336.94 v1@5242.61,336.94
FMC_TRIG3: R219.1 R247.1 | length 446.5
  Top Layer w5: v1(5589.01,512.07) R219.1@5593.72,516.77
  L7 SIG w5: v1(5242.61,386.3) 5243.24,386.94 5286.75,386.94 5327.61,346.09 5423.03,346.09 v1(5589.01,512.07)
  Bottom Layer w5: R247.1@5235.05,386.94 v1@5242.61,386.94
FMC_TRIG4: R228.1 R248.1 | length 354
  Top Layer w5: v1(5539.01,512.07) R228.1@5543.72,516.77
  L7 SIG w5: v1(5242.61,436.3) 5243.24,436.94 5382.87,436.94 5410.37,464.44 5511.89,464.44 5539.01,491.56 v1(5539.01,512.07)
  Bottom Layer w5: R248.1@5235.05,436.94 v1@5242.61,436.94
FMC_TRIGCLK: R222.1 R243.1 | length 1202.6
  Top Layer w5: R222.1@5539.01,1112.07 R222.1@5543.72,1107.36
  L7 SIG w5: v1(5242.61,486.3) 5243.24,486.94 5393.38,486.94 5463.96,557.52 5658.38,557.52 5680.51,579.65 5680.51,693.9 5620.85,753.57 5607.8,766.62 5496.04,766.62 5476.48,786.17 5476.48,838.9 5522.51,884.93 5522.51,918.9 5533.01,929.4 v1(5533.01,1118.07)
  Bottom Layer w5: R243.1@5235.05,486.94 v1@5242.61,486.94
FPGA_CORECLK_n: C167.1 J1.G7 | length 4446.8
  L10 SIG w3: v1(2657.26,1200.8) 2657.26,1208.07 2659.02,1209.82 2698.5,1209.82 2724.46,1183.86 3134.18,1183.86 3264.15,1053.9 3285.51,1053.9 3318.7,1020.72 3358.77,1020.72 3401.68,977.81 3427.37,977.81 3427.42,977.75 3430.27,977.75 ; 3430.29,977.78 3447.15,977.78 ; 3447.18,977.75 3556.47,977.75 3590.37,1011.65 3697.2,1011.65 3738.1,970.75 3830.92,970.75 3830.98,970.69 3868.29,970.69 3872.95,966.04 3882.55,956.43 3885.98,953.01 3886.79,953.01 3906.77,933.03 3937.59,933.03 3938.41,932.21 4030.28,932.21 4057.24,959.17 4117.17,959.17 4117.9,959.89 4123.69,959.89 4146.52,937.07 4176.22,937.07 4183.49,929.79 4370.02,929.79 4410.97,970.75 4590.31,970.75 4627.65,1008.09 5078.63,1008.09 5504.54,1434 5716.29,1434 5785.51,1503.22 5785.51,1970.12 5741.83,2013.8 5585.86,2013.8 5572.11,2027.55 5572.11,2041.67 5589.01,2058.57 5612.25,2058.57 5614.01,2056.81 v1(5614.01,2037.07)
  Bottom Layer w6.3: C167.1@2605.66,1285.55 cw(c2605.66,1278.93) 2612.28,1278.93 2612.28,1235.89 ccw(c2640.75,1235.89) 2640.75,1207.42 2650.64,1207.42 cw(c2650.64,1200.8) v1(2657.26,1200.8)
FPGA_CORECLK_p: C166.1 J1.G6 | length 4428.3
  L10 SIG w3: v1(2657.26,1225.85) 2657.26,1218.58 2659.02,1216.82 2701.4,1216.82 2727.36,1190.86 3137.08,1190.86 3267.05,1060.9 3288.41,1060.9 3321.6,1027.72 3361.67,1027.72 3404.58,984.81 3430.27,984.81 ; 3430.29,984.78 3450.05,984.78 ; 3450.08,984.75 3553.57,984.75 3587.48,1018.65 3700.1,1018.65 3741,977.75 3833.82,977.75 3833.88,977.69 3871.19,977.69 3879.95,968.94 3887.5,961.38 3888.88,960.01 3889.69,960.01 3909.67,940.03 3940.49,940.03 3941.31,939.21 4027.38,939.21 4054.34,966.17 4114.27,966.17 4115,966.89 4126.59,966.89 4149.42,944.07 4179.12,944.07 4186.39,936.79 4367.12,936.79 4408.07,977.75 4587.41,977.75 4624.75,1015.09 5075.73,1015.09 5501.64,1441 5713.39,1441 5778.51,1506.12 5778.51,1967.22 5738.93,2006.8 5582.96,2006.8 5565.11,2024.65 5565.11,2044.57 5586.11,2065.57 5612.25,2065.57 5614.01,2067.32 v1(5614.01,2087.07)
  Bottom Layer w6.3: C166.1@2630.71,1285.55 ccw(c2630.71,1278.93) 2624.08,1278.93 2624.08,1235.89 ccw(c2640.75,1235.89) 2640.75,1219.22 2650.64,1219.22 ccw(c2650.64,1225.85) v1(2657.26,1225.85)
FPGA_SYSREF_n: C175.1 J1.G10 | length 4463.5
  L10 SIG w3: v1(2661.86,1865.81) 2661.86,1871.64 2665.06,1874.84 2724.29,1874.84 2778.39,1820.74 2778.39,1723.5 3354.02,1147.88 3354.02,1101.36 3378.67,1076.71 3457.99,1076.71 3461.64,1073.06 3725.46,1073.06 3793.83,1004.69 3864.86,1004.69 3869.41,1000.14 3927.34,1000.14 3940.59,986.89 3979.47,986.89 4004.16,1011.58 4101.69,1011.58 4146.38,966.89 4242.41,966.89 4274.57,999.06 4526.38,999.06 4565.5,1038.18 4996.03,1038.18 5370.86,1413.01 5427.53,1413.01 5515.09,1500.57 5706.5,1500.57 5745.93,1539.99 5745.93,1839.97 5722.1,1863.8 5596.83,1863.8 5583.51,1877.12 5583.51,1898.41 5593.67,1908.57 5612.25,1908.57 5614.01,1906.81 v1(5614.01,1887.07)
  Bottom Layer w6.3: C175.1@2635.71,1806.11 cw(c2635.71,1812.73) 2629.08,1812.73 2629.08,1855.77 cw(c2645.75,1855.77) 2645.75,1872.44 2655.64,1872.44 cw(c2655.64,1865.81) v1@2662.26,1865.81
FPGA_SYSREF_p: C174.1 J1.G9 | length 4482
  L10 SIG w3: v1(2661.86,1890.86) 2661.86,1885.03 2665.06,1881.84 2727.19,1881.84 2785.39,1823.63 2785.39,1726.4 3361.02,1150.78 3361.02,1104.26 3381.57,1083.71 3460.89,1083.71 3464.54,1080.06 3728.36,1080.06 3796.73,1011.69 3867.76,1011.69 3872.31,1007.14 3930.24,1007.14 3943.49,993.89 3976.57,993.89 4001.27,1018.58 4104.59,1018.58 4149.28,973.89 4239.51,973.89 4271.67,1006.06 4523.48,1006.06 4562.61,1045.18 4993.13,1045.18 5367.96,1420.01 5424.63,1420.01 5512.19,1507.57 5703.6,1507.57 5738.93,1542.89 5738.93,1837.07 5719.2,1856.8 5593.93,1856.8 5576.51,1874.22 5576.51,1901.3 5590.77,1915.57 5612.25,1915.57 5614.01,1917.32 v1(5614.01,1937.07)
  Bottom Layer w6.3: C174.1@2610.66,1806.11 ccw(c2610.66,1812.73) 2617.28,1812.73 2617.28,1855.77 cw(c2645.75,1855.77) 2645.75,1884.24 2655.64,1884.24 ccw(c2655.64,1890.86) v1@2662.26,1890.86
FTDI_I2C_SCL: R98.2 U36.3 U43.4 | length 464.8
  L10 SIG w5: v1(816.3,2356.07) 817.23,2355.13 828.7,2355.13 1025.67,2158.16 1032.58,2158.16 1043.65,2147.08 v1(1116.57,2147.08)
  Bottom Layer w5: U36.3@816.3,2318.07 v1(816.3,2356.07) ; v1(1116.57,2147.08) U43.4@1156.57,2147.08
GA0_FMC: J1.C34 R195.2 U61.1 | length 802.1
  Top Layer w10: U61.1@5971.65,258.79 5986.41,258.79 5991.41,253.79 v1(6006.65,253.79)
  L7 SIG w5: v1(5814.01,687.07) 5839.71,661.36 6025.03,661.36 6075.09,611.3 6075.09,241.3 6052.59,218.8 6024.01,218.8 6006.65,236.16 v1(6006.65,253.79)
